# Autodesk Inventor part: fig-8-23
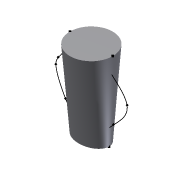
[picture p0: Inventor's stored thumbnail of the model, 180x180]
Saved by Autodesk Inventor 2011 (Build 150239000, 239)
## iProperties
Shininess: 64.0
Length Units: 11269
Angle Units: 11279
Time Units: 11290
Mass Units: 11283
Length Display Precision: 3
Angle Display Precision: 2
Compacted: True
Part Number: fig-8-23
Document SubType Name: Modeling
Created: 2002-12
Designer: deepak
Density: 1 g/cm^3
Density: 0.0
Volumn: 0.0
Area: 0.0
PropertySet Name: Model Information
Control State: 0
Master: False
Checked Out: False
Author: deepak
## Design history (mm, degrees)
sketch "Sketch1"
  geometry: 2 further points; 1 other entity
  constraints: 1 coincident, 3 other
workplane "Work Plane1"
workplane "Work Plane2"
sketch "Sketch3"
  geometry: C1 r 60 at (0, 0); 1 further point
  constraints: 1 centre point, 1 coincident, 1 other
sketch "Sketch4"
  geometry: 8 further points
  constraints: 8 other
sketch "Sketch5"
  geometry: 6 further points
  constraints: 6 other
sketch "Sketch6"
  geometry: 6 further points
  constraints: 6 other
  dimensions: "d20" = 35 distance of point (0, 0) point (-35, 0); "d21" = 0 vertical distance of point (0, 0) point (-35, 0); "d22" = 225 vertical distance of point (0, 0) point (-60, 225); "d23" = 60 horizontal distance of point (0, 0) point (-60, 225); "d24" = 100 horizontal distance of point (0, 0) point (-100, 125); "d25" = 125 vertical distance of point (0, 0) point (-100, 125)
loft "Loft4" dims "d50" = 0, "d51" = 90 deg, "d52" = 0, "d53" = 90 deg
body "Solid1"
other parameters: "d5" = 125
